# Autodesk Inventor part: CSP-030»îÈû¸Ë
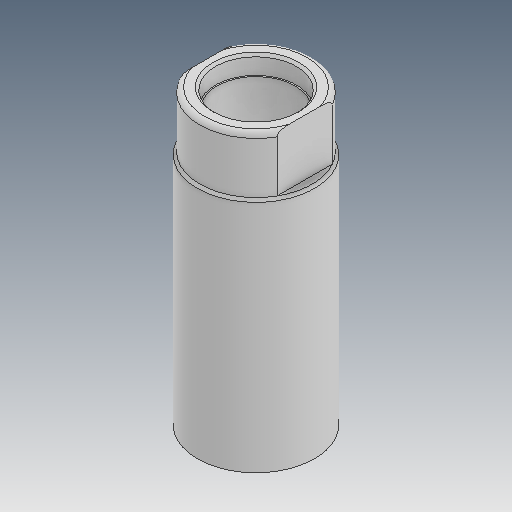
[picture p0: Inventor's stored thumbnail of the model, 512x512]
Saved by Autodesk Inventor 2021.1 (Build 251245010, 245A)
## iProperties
Created: 2019-01
Part Number: CSP-030»îÈû¸Ë
Material: Ogólny
Document SubType Name: Modeling
Designer: user
Density: 1 g/cm^3
Appearance: Domyślna
Author: user
Revision Number: ÈÎºÎ
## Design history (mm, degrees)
feature "ÇÐ³ý-À­Éì4"
node "Bryła1"
